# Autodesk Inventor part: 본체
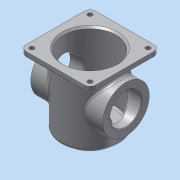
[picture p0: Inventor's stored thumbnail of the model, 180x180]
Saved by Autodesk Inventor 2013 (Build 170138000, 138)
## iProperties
Created: 2015-10
Part Number: 본체
Material: 알루미늄 6061
Document SubType Name: Modeling
Designer: dgall
Density: 2.71 g/cm^3
Mass: 985.996 g
Surface Area: 1037.37 cm^2
Volume: 363.836 cm^3
Author: dgall
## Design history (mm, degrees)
sketch "스케치1"
  geometry: C1 r 50 at (0, 0); 1 further point
  constraints: 1 centre point, 1 coincident
  dimensions: "d0" = 100 diameter of C1
extrude "돌출1" new body sketch "스케치1" distance "d1" = 120; taper "d2" = 0 deg
sketch "스케치2"
  geometry: L1 (-60, 60)-(60, 60); L2 (60, 60)-(60, -60); L3 (60, -60)-(-60, -60); L4 (-60, -60)-(-60, 60); C1 r 50 at (0, 0) reference; 2 further points
  constraints: 8 end point, 2 midpoint, 2 parallel, 2 perpendicular, 1 horizontal, 1 horizontal alignment, 1 vertical alignment
  dimensions: "d3" = 120 distance of L1.start L1.end
extrude "돌출2" join sketch "스케치2" distance "d5" = 10; taper "d6" = 0 deg
fillet "모깎기1" dims "d7" = 10
sketch "스케치3"
  geometry: A1 r 10 centre (50, -50) between (50, -60) and (60, -50) reference; A2 r 10 centre (50, 50) between (60, 50) and (50, 60) reference; A3 r 10 centre (-50, 50) between (-50, 60) and (-60, 50) reference; A4 r 10 centre (-50, -50) between (-60, -50) and (-50, -60) reference
hole "구멍1" sketch "스케치3" at (50, 50), (50, -50), (-50, 50), (-50, -50) diameter "d8" = 8; stored, may be unused: countersink angle "d12" = 90 deg, drill point angle "d14" = 118 deg; dims "d9" = 6, "d10" = 4, "d11" = 2, "d13" = 8
sketch "스케치4"
  geometry: C1 r 50 at (0, 0) reference; C2 r 40 at (0, 0)
  constraints: 1 centre point, 1 coincident
  dimensions: "d15" = 80 diameter of C2
extrude "돌출3" join sketch "스케치4" distance "d16" = 5; taper "d17" = 0 deg
sketch "스케치5"
  geometry: L1 (0, 0)-(0, 40); L2 (0, 0)-(22.981, 22.981); 1 further point
  constraints: 4 end point, 1 coincident, 1 vertical, 1 vertical alignment, 1 other
  dimensions: "d18" = 45 deg angle of L2 L1; "d19" = 32.5 distance of L1.start L2.end
hole "구멍2" sketch "스케치5" at (22.981, 22.981) diameter "d20" = 3.242; stored, may be unused: countersink angle "d24" = 90 deg, drill point angle "d26" = 118 deg; dims "d21" = 8, "d22" = 4, "d23" = 2, "d25" = 10
sketch "스케치7"
  geometry: C1 r 40 at (0, 0) reference; C2 r 27 at (0, 0)
  constraints: 1 centre point, 1 coincident
  dimensions: "d32" = 54 diameter of C2
extrude "돌출4" cut sketch "스케치7" distance "d33" = 13; taper "d34" = 0 deg
sketch "스케치8"
  geometry: C1 r 45 at (0, 0); 1 further point
  constraints: 1 centre point, 1 coincident
  dimensions: "d35" = 90 diameter of C1
extrude "돌출5" cut sketch "스케치8" distance "d36" = 112; taper "d37" = 0 deg
chamfer "모따기1" distance "d38" = 3; stored, may be unused: second distance "d39" = 2, angle "d40" = 45 deg
chamfer "모따기2" distance "d41" = 1; stored, may be unused: second distance "d42" = 2, angle "d43" = 45 deg
fillet "모깎기2" dims "d44" = 5
fillet "모깎기3" dims "d45" = 5
fillet "모깎기4" dims "d46" = 3
fillet "모깎기5" dims "d47" = 3
fillet "모깎기6" dims "d48" = 3
node "작업 평면1"
sketch "스케치9"
  geometry: L1 (50, 0)-(-50, 0) reference; 3 further points
  constraints: 1 midpoint, 1 vertical alignment, 1 other
  dimensions: "d49" = 70 distance from line of point (0, -70) L1
feature "엠보싱1" sketch "스케치9" dims "d50" = 0.5, "d51" = 0
node "작업 평면5"
  node "작업 평면4"
sketch "스케치12"
  geometry: C1 r 40 at (-60, 0); 1 further point
  constraints: 1 centre point, 1 horizontal alignment
  dimensions: "d65" = 80 diameter of C1; "d66" = 60 distance of point (0, 0) C1.centre
extrude "돌출8" join sketch "스케치12" stored distance "d67" = 112; taper "d68" = 0 deg
sketch "스케치13"
  geometry: C1 r 40 at (0, 0) reference; C2 r 27 at (0, 0); 1 further point
  constraints: 1 centre point, 1 coincident
  dimensions: "d69" = 54 diameter of C2
extrude "돌출9" cut sketch "스케치13" stored distance "d70" = 112; taper "d71" = 0 deg
chamfer "모따기3" distance "d72" = 1; stored, may be unused: second distance "d73" = 2, angle "d74" = 45 deg
fillet "모깎기9" dims "d75" = 3
sketch "스케치14"
  geometry: C1 r 40 at (0, 0) reference; 2 further points
  constraints: 1 vertical alignment
  dimensions: "d76" = 32.5 distance of point (0, 32.5) C1.centre
hole "구멍3" sketch "스케치14" at (0, 32.5) diameter "d77" = 3.242; stored, may be unused: countersink angle "d81" = 90 deg, drill point angle "d83" = 118 deg; dims "d78" = 8, "d79" = 4, "d80" = 2, "d82" = 10
fillet "모깎기10" dims "d87" = 5
node "솔리드1"
pattern_circular "원형 패턴1" dims angle "d28" = 360 deg
mirror "대칭2"
mirror "대칭3"
pattern_circular "원형 패턴2" dims angle "d85" = 360 deg
other parameters: "d63" = 90 deg, "d64" = 62
